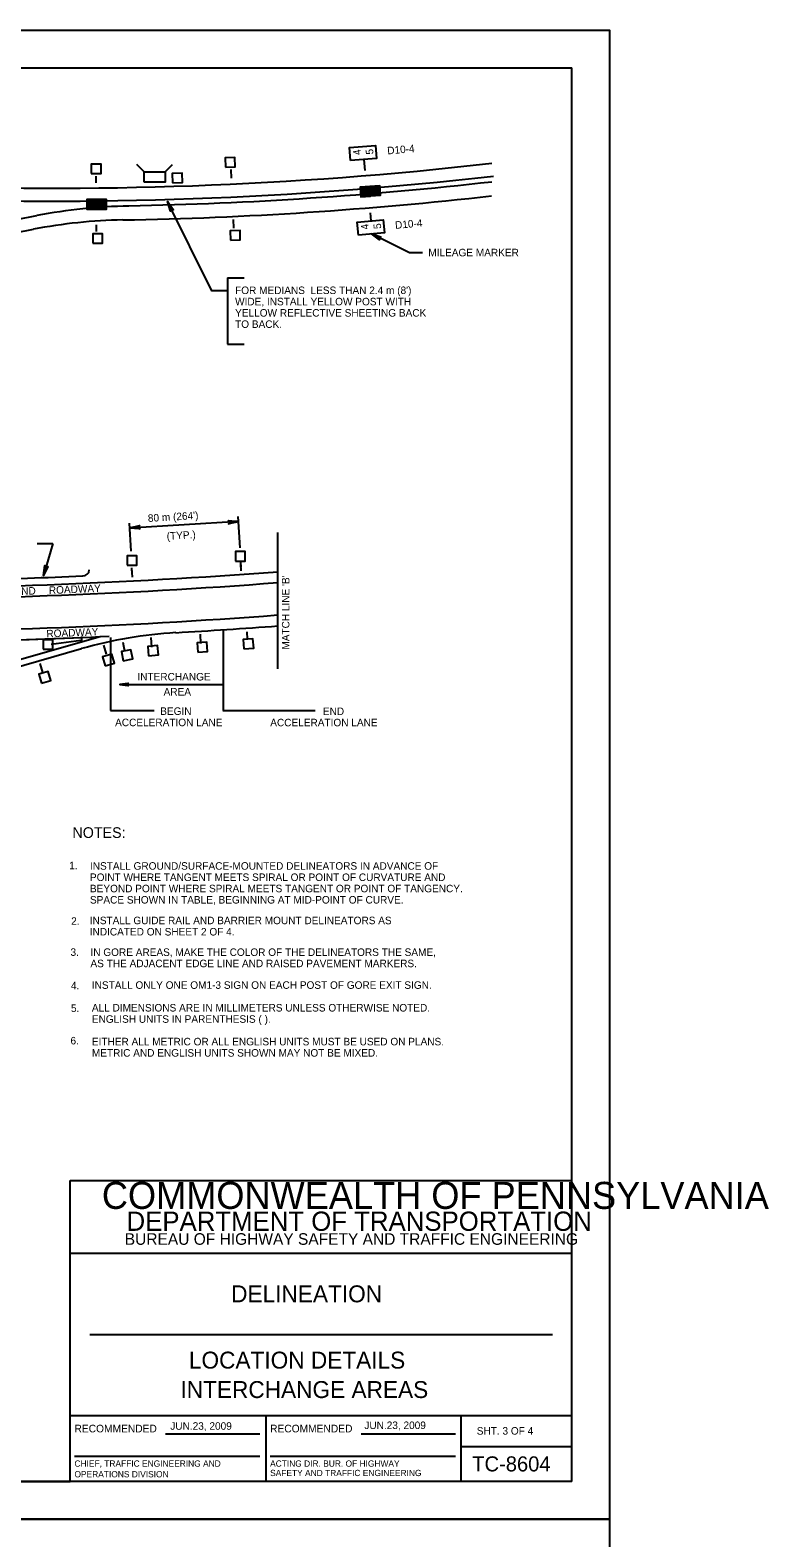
# Model space of a CAD drawing. Extents: x 640253 to 641999, y 298458 to 299646.
# Drawn here: x 641704 to 641999, y 299044 to 299646 of the extents above; entities that cross this region are included whole.
import ezdxf

# ---------------------------------------------------------------- set-up
doc = ezdxf.new("R2010")
doc.units = 0
for name, color, linetype in [('1', 7, 'Continuous'), ('2', 7, 'Continuous'), ('PLT-BNDY', 7, 'Continuous')]:
    doc.layers.add(name, color=color, linetype=linetype)

msp = doc.modelspace()

# ---------------------------------------------------------------- linework, layer by layer
at = {"layer": '1'}
for p, q in [((641134.31, 299630.63), (641920.31, 299630.63)), ((641920.31, 299066.63), (641920.31, 299630.63)), ((641720.31, 299066.63), (641720.31, 299186.63)), ((641720.31, 299186.63), (641920.31, 299186.63)), ((641920.31, 299157.63), (641720.31, 299157.63)), ((641728.06, 299125.31), (641912.56, 299125.31)), ((641720.31, 299093), (641920.31, 299093)), ((641798.31, 299093), (641798.31, 299066.63)), ((641876.19, 299066.63), (641876.19, 299093)), ((641758.24, 299085.57), (641795.87, 299085.57)), ((641836.24, 299085.57), (641873.87, 299085.57)), ((641876.19, 299080.63), (641920.31, 299080.63)), ((641721.99, 299076.68), (641795.87, 299076.68)), ((641799.99, 299076.68), (641873.87, 299076.68)), ((641920.31, 299066.63), (641134.31, 299066.63)), ((641134.31, 299066.63), (641720.31, 299066.63))]:
    msp.add_line(p, q, dxfattribs=at)
at = {"layer": '2'}
for p, q in [((641749.79, 299589.1), (641746.85, 299592.04)), ((641758.12, 299589.1), (641761.06, 299592.04)), ((641784.66, 299586.64), (641784.49, 299590.04)), ((641837.89, 299589.6), (641837.54, 299594.04)), ((641730.6, 299584.77), (641730.59, 299587.43)), ((641672.93, 299565.02), (641707.01, 299571.63)), ((641840.27, 299569.56), (641840.02, 299572.73)), ((641674.04, 299560.09), (641705.59, 299566.17)), ((641730.82, 299565.25), (641730.79, 299567.92)), ((641785.59, 299566.63), (641785.43, 299570.02)), ((641782.99, 299546.75), (641789.62, 299546.75)), ((641782.99, 299546.75), (641782.99, 299520.41)), ((641782.99, 299520.41), (641789.62, 299520.41)), ((641788.1, 299439.07), (641787.2, 299451.66)), ((641744.54, 299437.76), (641743.89, 299448.92)), ((641787.38, 299449.54), (641744, 299446.98)), ((641803.08, 299390.85), (641803.08, 299445.17)), ((641707.16, 299440.83), (641713.41, 299440.83)), ((641713.41, 299440.83), (641709.61, 299428.01)), ((641788.5, 299429.87), (641788.3, 299432.76)), ((641788.42, 299431.48), (641788.31, 299433.25)), ((641745.08, 299427.35), (641744.89, 299431.15)), ((641744.99, 299428.96), (641744.89, 299430.73)), ((641589.09, 299362.8), (641732.18, 299403.67)), ((641724.87, 299401.52), (641724.87, 299403.72)), ((641736.33, 299403.34), (641736.33, 299374.22)), ((641752.77, 299399.47), (641752.58, 299403.27)), ((641772.43, 299400.9), (641772.24, 299404.7)), ((641781.29, 299406.17), (641781.29, 299374.22)), ((641791.02, 299402.7), (641790.81, 299405.6)), ((641593.29, 299361.29), (641724.82, 299398.87)), ((641712.74, 299400.65), (641724.72, 299402.27)), ((641733.54, 299400.24), (641734.58, 299396.61)), ((641741.21, 299401.43), (641741.92, 299397.81)), ((641708.19, 299393), (641709.24, 299389.37)), ((641740.07, 299384.62), (641781.29, 299384.62)), ((641736.33, 299374.22), (641753.7, 299374.22)), ((641781.17, 299374.22), (641817.92, 299374.22))]:
    msp.add_line(p, q, dxfattribs=at)
for points in [[(641832.07, 299593.57), (641831.62, 299598.75), (641842, 299599.65), (641842.45, 299594.47)], [(641728.69, 299588.38), (641732.59, 299588.38), (641732.59, 299592.13), (641728.69, 299592.13)], [(641782.22, 299591), (641786.11, 299591.14), (641785.98, 299594.88), (641782.09, 299594.75)], [(641749.79, 299584.93), (641749.79, 299589.1), (641758.12, 299589.1), (641758.12, 299584.93)], [(641761.13, 299584.75), (641765.02, 299584.89), (641764.89, 299588.63), (641761, 299588.49)], [(641784.23, 299561.88), (641788.12, 299562.01), (641787.99, 299565.76), (641784.1, 299565.62)], [(641835.19, 299563.86), (641834.74, 299569.04), (641845.12, 299569.94), (641845.57, 299564.76)], [(641729.32, 299560.61), (641733.21, 299560.61), (641733.21, 299564.36), (641729.32, 299564.36)], [(641742.99, 299432.2), (641746.89, 299432.2), (641746.89, 299435.95), (641742.99, 299435.95)], [(641786.14, 299433.82), (641790.04, 299433.82), (641790.04, 299437.57), (641786.14, 299437.57)], [(641789.56, 299398.75), (641793.45, 299399.08), (641793.12, 299402.82), (641789.24, 299402.48)], [(641709.51, 299398.7), (641713.41, 299398.7), (641713.41, 299402.45), (641709.51, 299402.45)], [(641734.21, 299391.99), (641737.96, 299393.06), (641736.93, 299396.66), (641733.18, 299395.59)], [(641741.41, 299394), (641745.23, 299394.75), (641744.52, 299398.42), (641740.7, 299397.68)], [(641751.56, 299396.06), (641755.44, 299396.46), (641755.05, 299400.19), (641751.18, 299399.78)], [(641771.2, 299397.43), (641775.08, 299397.77), (641774.75, 299401.51), (641770.87, 299401.17)], [(641708.8, 299385.13), (641712.55, 299386.2), (641711.52, 299389.8), (641707.77, 299388.73)]]:
    msp.add_lwpolyline(points, close=True, dxfattribs=at)
for points in [[(641836.14, 299579.19), (641840.03, 299579.46), (641839.77, 299583.2), (641835.88, 299582.92), (641836.14, 299579.19), (641839.71, 299583.12), (641835.95, 299582.86), (641836.2, 299579.24), (641839.96, 299579.51), (641839.72, 299583.06), (641836.03, 299582.8), (641836.27, 299579.31), (641839.88, 299579.57), (641839.63, 299582.96), (641836.1, 299582.71), (641836.34, 299579.38), (641839.81, 299579.62), (641839.58, 299582.9), (641836.18, 299582.66), (641836.4, 299579.44), (641839.73, 299579.68), (641839.5, 299582.82), (641836.25, 299582.6), (641836.46, 299579.5), (641839.66, 299579.75), (641839.42, 299582.74), (641836.33, 299582.53), (641836.52, 299579.57), (641839.58, 299579.81), (641839.36, 299582.67), (641836.4, 299582.46), (641836.57, 299579.66), (641839.49, 299579.89), (641839.3, 299582.58), (641836.49, 299582.39), (641836.64, 299579.71), (641839.38, 299579.95), (641839.22, 299582.51), (641836.57, 299582.33), (641836.71, 299579.78), (641839.3, 299580.01), (641839.13, 299582.45), (641836.66, 299582.25), (641836.79, 299579.83), (641839.21, 299580.07), (641839.04, 299582.36), (641836.75, 299582.17), (641836.78, 299581.07), (641836.86, 299579.91), (641839.13, 299580.14), (641838.95, 299582.26), (641836.84, 299582.07), (641836.94, 299579.99), (641839.04, 299580.2), (641838.87, 299582.17), (641836.95, 299581.98), (641837.04, 299580.08), (641838.91, 299580.26), (641838.76, 299582.04), (641837.09, 299581.88), (641837.15, 299580.22), (641838.75, 299580.36), (641838.62, 299581.92), (641837.26, 299581.77), (641837.28, 299580.34), (641837.29, 299580.34), (641838.6, 299580.49), (641838.5, 299581.77), (641837.4, 299581.65), (641837.42, 299580.48), (641838.43, 299580.61), (641838.37, 299581.6), (641837.55, 299581.53), (641837.57, 299580.65), (641838.27, 299580.73), (641838.19, 299581.46), (641837.72, 299581.4), (641837.75, 299580.8), (641838.08, 299580.85), (641838.05, 299581.3), (641837.91, 299581.31), (641837.91, 299580.95)], [(641840.07, 299579.5), (641843.97, 299579.77), (641843.7, 299583.51), (641839.81, 299583.24), (641840.07, 299579.5), (641843.64, 299583.44), (641839.88, 299583.17), (641840.14, 299579.56), (641843.9, 299579.82), (641843.65, 299583.37), (641839.97, 299583.11), (641840.21, 299579.63), (641843.82, 299579.89), (641843.57, 299583.28), (641840.04, 299583.03), (641840.27, 299579.7), (641843.74, 299579.94), (641843.52, 299583.21), (641840.11, 299582.98), (641840.34, 299579.76), (641843.66, 299580), (641843.43, 299583.14), (641840.18, 299582.91), (641840.39, 299579.82), (641843.59, 299580.06), (641843.36, 299583.06), (641840.26, 299582.84), (641840.45, 299579.89), (641843.52, 299580.13), (641843.3, 299582.99), (641840.33, 299582.78), (641840.51, 299579.97), (641843.42, 299580.2), (641843.23, 299582.89), (641840.43, 299582.71), (641840.57, 299580.03), (641843.32, 299580.27), (641843.15, 299582.83), (641840.51, 299582.64), (641840.64, 299580.1), (641843.24, 299580.32), (641843.07, 299582.76), (641840.59, 299582.57), (641840.72, 299580.15), (641843.14, 299580.39), (641842.98, 299582.68), (641840.68, 299582.49), (641840.71, 299581.39), (641840.79, 299580.22), (641843.06, 299580.46), (641842.88, 299582.57), (641840.77, 299582.39), (641840.87, 299580.3), (641842.97, 299580.52), (641842.8, 299582.49), (641840.88, 299582.3), (641840.98, 299580.4), (641842.84, 299580.58), (641842.7, 299582.35), (641841.03, 299582.2), (641841.08, 299580.53), (641842.69, 299580.67), (641842.56, 299582.24), (641841.19, 299582.09), (641841.21, 299580.66), (641841.22, 299580.66), (641842.53, 299580.8), (641842.43, 299582.08), (641841.33, 299581.97), (641841.35, 299580.8), (641842.37, 299580.93), (641842.31, 299581.92), (641841.48, 299581.84), (641841.5, 299580.96), (641842.2, 299581.04), (641842.12, 299581.78), (641841.66, 299581.72), (641841.68, 299581.11), (641842.02, 299581.17), (641841.99, 299581.61), (641841.84, 299581.63), (641841.84, 299581.27)], [(641726.93, 299574.27), (641730.83, 299574.27), (641730.83, 299578.01), (641726.93, 299578.01), (641726.93, 299574.27), (641730.77, 299577.94), (641727, 299577.94), (641727, 299574.32), (641730.77, 299574.32), (641730.77, 299577.88), (641727.07, 299577.88), (641727.07, 299574.39), (641730.69, 299574.39), (641730.68, 299577.79), (641727.14, 299577.79), (641727.14, 299574.44), (641730.62, 299574.44), (641730.62, 299577.73), (641727.21, 299577.73), (641727.21, 299574.5), (641730.54, 299574.51), (641730.53, 299577.66), (641727.28, 299577.66), (641727.27, 299574.56), (641730.48, 299574.58), (641730.46, 299577.59), (641727.35, 299577.59), (641727.34, 299574.63), (641730.41, 299574.65), (641730.39, 299577.52), (641727.42, 299577.52), (641727.4, 299574.71), (641730.32, 299574.73), (641730.32, 299577.42), (641727.51, 299577.44), (641727.47, 299574.75), (641730.22, 299574.8), (641730.23, 299577.37), (641727.58, 299577.37), (641727.54, 299574.82), (641730.14, 299574.86), (641730.14, 299577.31), (641727.66, 299577.29), (641727.62, 299574.86), (641730.06, 299574.93), (641730.05, 299577.23), (641727.75, 299577.2), (641727.7, 299576.1), (641727.7, 299574.93), (641729.98, 299575.01), (641729.95, 299577.13), (641727.83, 299577.1), (641727.79, 299575.01), (641729.89, 299575.08), (641729.86, 299577.06), (641727.93, 299577), (641727.89, 299575.1), (641729.76, 299575.14), (641729.75, 299576.93), (641728.07, 299576.89), (641728.01, 299575.22), (641729.62, 299575.25), (641729.6, 299576.82), (641728.22, 299576.76), (641728.15, 299575.34), (641728.16, 299575.34), (641729.47, 299575.39), (641729.46, 299576.67), (641728.36, 299576.64), (641728.29, 299575.47), (641729.32, 299575.53), (641729.32, 299576.52), (641728.5, 299576.5), (641728.46, 299575.62), (641729.16, 299575.65), (641729.13, 299576.39), (641728.67, 299576.36), (641728.64, 299575.76), (641728.99, 299575.79), (641728.99, 299576.24), (641728.84, 299576.27), (641728.82, 299575.91)], [(641730.87, 299574.27), (641734.77, 299574.27), (641734.77, 299578.01), (641730.87, 299578.01), (641730.87, 299574.27), (641734.7, 299577.94), (641730.93, 299577.94), (641730.93, 299574.32), (641734.7, 299574.32), (641734.7, 299577.88), (641731.01, 299577.88), (641731.01, 299574.39), (641734.62, 299574.39), (641734.62, 299577.79), (641731.08, 299577.79), (641731.08, 299574.44), (641734.56, 299574.44), (641734.56, 299577.73), (641731.15, 299577.73), (641731.15, 299574.5), (641734.48, 299574.51), (641734.47, 299577.66), (641731.21, 299577.66), (641731.2, 299574.56), (641734.41, 299574.58), (641734.39, 299577.59), (641731.28, 299577.59), (641731.27, 299574.63), (641734.34, 299574.65), (641734.32, 299577.52), (641731.35, 299577.52), (641731.33, 299574.71), (641734.26, 299574.73), (641734.26, 299577.42), (641731.44, 299577.44), (641731.4, 299574.75), (641734.16, 299574.81), (641734.17, 299577.37), (641731.52, 299577.37), (641731.48, 299574.82), (641734.08, 299574.86), (641734.08, 299577.31), (641731.59, 299577.29), (641731.56, 299574.86), (641733.99, 299574.93), (641733.98, 299577.23), (641731.68, 299577.2), (641731.63, 299576.1), (641731.63, 299574.93), (641733.91, 299575.01), (641733.88, 299577.14), (641731.76, 299577.1), (641731.72, 299575.01), (641733.83, 299575.08), (641733.8, 299577.06), (641731.87, 299577), (641731.83, 299575.1), (641733.7, 299575.14), (641733.68, 299576.93), (641732, 299576.89), (641731.95, 299575.22), (641733.55, 299575.25), (641733.53, 299576.82), (641732.16, 299576.76), (641732.08, 299575.34), (641732.09, 299575.34), (641733.41, 299575.39), (641733.4, 299576.68), (641732.29, 299576.64), (641732.23, 299575.47), (641733.25, 299575.53), (641733.26, 299576.52), (641732.43, 299576.5), (641732.39, 299575.62), (641733.09, 299575.65), (641733.07, 299576.39), (641732.6, 299576.36), (641732.58, 299575.76), (641732.92, 299575.79), (641732.92, 299576.24), (641732.77, 299576.27), (641732.75, 299575.91)], [(641782.99, 299541.63), (641776.74, 299541.63), (641759.14, 299577.21)], [(641760.39, 299573.6), (641760.58, 299573.85), (641759.14, 299577.21), (641760.39, 299573.6), (641760.33, 299573.35), (641759.14, 299577.21), (641760.91, 299574.02), (641761.22, 299574.02), (641759.14, 299577.21), (641761.47, 299573.92), (641761.22, 299574.02)], [(641860.81, 299556.75), (641855.6, 299556.75), (641840.38, 299564.31)], [(641843.57, 299562.22), (641843.54, 299562.52), (641840.38, 299564.31), (641843.57, 299562.22), (641843.65, 299561.99), (641840.38, 299564.31), (641843.72, 299562.86), (641843.96, 299563.05), (641840.38, 299564.31), (641844.21, 299563.12), (641843.96, 299563.05)], [(641747.81, 299446.87), (641747.65, 299447.14), (641744, 299447.12), (641747.81, 299446.87), (641748.01, 299446.72), (641744, 299447.12), (641747.62, 299447.52), (641747.74, 299447.8), (641744, 299447.12), (641747.93, 299447.99), (641747.74, 299447.8)], [(641783.57, 299449.79), (641783.73, 299449.52), (641787.38, 299449.54), (641783.57, 299449.79), (641783.37, 299449.94), (641787.38, 299449.54), (641783.75, 299449.14), (641783.64, 299448.87), (641787.38, 299449.54), (641783.44, 299448.67), (641783.64, 299448.87)], [(641711.14, 299431.51), (641710.84, 299431.45), (641709.61, 299428.01), (641711.14, 299431.51), (641711.35, 299431.65), (641709.61, 299428.01), (641710.47, 299431.56), (641710.25, 299431.76), (641709.61, 299428.01), (641710.13, 299432.01), (641710.25, 299431.76)], [(641743.22, 299384.23), (641743.1, 299384.45), (641740.07, 299384.62), (641743.22, 299384.23), (641743.38, 299384.09), (641740.07, 299384.62), (641743.1, 299384.78), (641743.21, 299385.01), (641740.07, 299384.62), (641743.38, 299385.15), (641743.21, 299385.01)]]:
    msp.add_lwpolyline(points, dxfattribs=at)
for centre, radius, start, end in [((641713.53, 301122.08), 1539.51, 267.61256, 276.52429), ((641713.53, 301122.08), 1544.66, 267.61256, 276.52429), ((641713.53, 301122.08), 1546.82, 271.11716, 276.48929), ((641713.53, 301122.08), 1552.43, 271.024, 276.46547), ((641747.52, 299361.36), 214.14, 91.02364, 100.90658), ((641745, 299361.65), 208.29, 91.02364, 100.90658), ((641618.76, 301866.5), 2443.88, 270.0023, 274.32557), ((641617.17, 301869.36), 2443.88, 271.50321, 272.53479), ((641725.38, 299430.4), 2.53, 267.21992, 357.13947), ((641618.76, 301866.5), 2448.22, 270.0023, 274.31789), ((641618.76, 301866.5), 2461.1, 270.0023, 274.29526), ((641618.76, 301866.5), 2465.44, 270.0023, 272.72047), ((641618.76, 301866.5), 2465.43, 270.0023, 272.63682), ((641772.51, 299231.98), 173.57, 93.34006, 105.94714), ((641618.76, 301866.5), 2465.44, 273.34006, 274.28767)]:
    msp.add_arc(centre, radius, start, end, dxfattribs=at)
at = {"layer": 'PLT-BNDY'}
for points in [[(641094.31, 299645.63), (641935.31, 299645.63), (641935.31, 299051.63), (641094.31, 299051.63)], [(641094.31, 299051.63), (641935.31, 299051.63), (641935.31, 298457.63), (641094.31, 298457.63)]]:
    msp.add_lwpolyline(points, close=True, dxfattribs=at)

# ---------------------------------------------------------------- texts
at = {"layer": '1'}
for s, height, p in [('COMMONWEALTH OF PENNSYLVANIA', 10.7828, (641732.9, 299175.36)), ('DEPARTMENT OF TRANSPORTATION', 7.6837, (641742.76, 299166.61)), ('BUREAU OF HIGHWAY SAFETY AND TRAFFIC ENGINEERING', 4.6253, (641742.04, 299161.04)), ('DELINEATION', 6.75, (641784.46, 299138.1)), ('LOCATION DETAILS', 6.75, (641767.61, 299111.66)), ('INTERCHANGE AREAS', 6.75, (641764.24, 299099.91)), ('JUN.23, 2009', 3, (641760.19, 299087.25)), ('JUN.23, 2009', 3, (641837.58, 299087.54)), ('RECOMMENDED', 3.048, (641721.99, 299086.2)), ('RECOMMENDED', 3.048, (641799.99, 299086.2)), ('SHT. 3 OF 4', 3, (641882.4, 299085.31)), ('CHIEF, TRAFFIC ENGINEERING AND', 2.5, (641721.99, 299072.51)), ('ACTING DIR. BUR. OF HIGHWAY', 2.5, (641799.99, 299072.51)), ('TC-8604', 6, (641880.6, 299070.63)), ('OPERATIONS DIVISION', 2.5, (641721.99, 299068.26)), ('SAFETY AND TRAFFIC ENGINEERING', 2.5, (641799.99, 299068.76))]:
    msp.add_text(s, height=height, dxfattribs=at).set_placement(p)
at = {"layer": '2'}
for s, rotation, p in [('4', 99.90169, (641836.32, 299596.04)), ('5', 94.93018, (641841.23, 299596.14)), ('D10-4', 4.92854, (641846.83, 299596.04)), ('4', 99.90169, (641839.43, 299566.33)), ('5', 94.93018, (641844.34, 299566.43)), ('D10-4', 4.92854, (641849.94, 299566.33)), ("80 m (264')", 3.36646, (641751.35, 299449.41)), ('(TYP.)', 3.36646, (641758.84, 299442.26)), ("MATCH LINE 'B'", 90, (641807.7, 299398.49)), ('WESTBOUND', 1.74068, (641680.51, 299419.69)), ('ROADWAY', 2.36512, (641711.82, 299420.65)), ('ROADWAY', 2.36512, (641710.85, 299403.33))]:
    msp.add_text(s, height=3, rotation=rotation, dxfattribs=at).set_placement(p)
for s, height, p in [('MILEAGE MARKER', 3, (641863.08, 299555.4)), ("FOR MEDIANS  LESS THAN 2.4 m (8') ", 3, (641786.03, 299540.34)), ('WIDE, INSTALL YELLOW POST WITH ', 3, (641786.03, 299535.84)), ('YELLOW REFLECTIVE SHEETING BACK ', 3, (641786.03, 299531.34)), ('TO BACK.', 3, (641786.03, 299526.84)), ('INTERCHANGE', 3, (641747.09, 299386.17)), ('AREA', 3, (641757.53, 299380.17)), ('BEGIN', 3, (641756.18, 299372.44)), ('END', 3, (641821.04, 299372.39)), ('ACCELERATION LANE', 3, (641738.19, 299367.94)), ('ACCELERATION LANE', 3, (641800.05, 299367.89)), ('NOTES:', 4.25, (641721.19, 299323.37)), ('1. ', 3, (641719.85, 299310.86)), ('INSTALL GROUND/SURFACE-MOUNTED DELINEATORS IN ADVANCE OF', 3, (641728.16, 299310.68)), ('POINT WHERE TANGENT MEETS SPIRAL OR POINT OF CURVATURE AND', 3, (641728.16, 299306.18)), ('BEYOND POINT WHERE SPIRAL MEETS TANGENT OR POINT OF TANGENCY.', 3, (641728.16, 299301.68)), ('SPACE SHOWN IN TABLE, BEGINNING AT MID-POINT OF CURVE.', 3, (641728.16, 299297.18)), ('2. ', 3, (641720.67, 299288.7)), ('INSTALL GUIDE RAIL AND BARRIER MOUNT DELINEATORS AS', 3, (641728.08, 299288.94)), ('INDICATED ON SHEET 2 OF 4.', 3, (641728.08, 299284.44)), ('3. ', 3, (641720.4, 299276.32)), ('IN GORE AREAS, MAKE THE COLOR OF THE DELINEATORS THE SAME,', 3, (641728.36, 299276.28)), ('AS THE ADJACENT EDGE LINE AND RAISED PAVEMENT MARKERS.', 3, (641728.36, 299271.78)), ('4. ', 3, (641720.59, 299262.97)), ('INSTALL ONLY ONE OM1-3 SIGN ON EACH POST OF GORE EXIT SIGN.', 3, (641728.92, 299263.16)), ('5. ', 3, (641720.59, 299253.93)), ('ALL DIMENSIONS ARE IN MILLIMETERS UNLESS OTHERWISE NOTED.  ', 3, (641728.92, 299254.11)), ('ENGLISH UNITS IN PARENTHESIS ( ).', 3, (641728.92, 299249.61)), ('6. ', 3, (641720.4, 299240.98)), ('EITHER ALL METRIC OR ALL ENGLISH UNITS MUST BE USED ON PLANS.  ', 3, (641728.92, 299240.61)), ('METRIC AND ENGLISH UNITS SHOWN MAY NOT BE MIXED.', 3, (641728.92, 299236.11))]:
    msp.add_text(s, height=height, dxfattribs=at).set_placement(p)

doc.saveas('drawing.dxf')
